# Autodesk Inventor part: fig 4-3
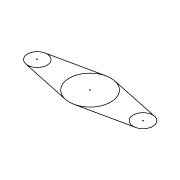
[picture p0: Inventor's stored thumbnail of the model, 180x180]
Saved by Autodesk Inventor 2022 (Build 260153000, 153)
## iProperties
Created: 2005-02
Part Number: fig 4-3
Document SubType Name: Modeling
Designer: CADCIM
Manufacturer: Standard
Standards Organization: Custom
Density: 1 g/cm^3
Material: Generic
Appearance: Default
Author: CADCIM
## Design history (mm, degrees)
sketch "Sketch1"
  geometry: L1 (-33.874, 5.844)-(-2.722, 12.469); L2 (2.595, 12.472)-(33.871, 5.852); L3 (-33.884, -5.902)-(-2.745, -12.585); L4 (2.595, -12.592)-(33.871, -5.972); A1 r 12.81 centre (-0.057, -0.06) between (-2.722, 12.469) and (2.595, 12.472); A2 r 6.006 centre (-32.624, -0.03) between (-33.874, 5.844) and (-33.884, -5.902); A3 r 6.043 centre (32.619, -0.06) between (33.871, 5.852) and (33.871, -5.972)
  constraints: 8 end point, 8 point on circle, 8 tangent, 3 centre point, 1 other
